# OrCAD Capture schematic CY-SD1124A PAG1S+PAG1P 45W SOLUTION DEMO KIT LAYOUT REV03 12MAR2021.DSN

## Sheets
1 PAGE02_PULSE TRANSFORMER BOARD: size A4; title: CYPRESS 45W MOBILE CHARGER DEMO KIT CY-SD1124A; rev: 03; note: 630-XXXXX-XX
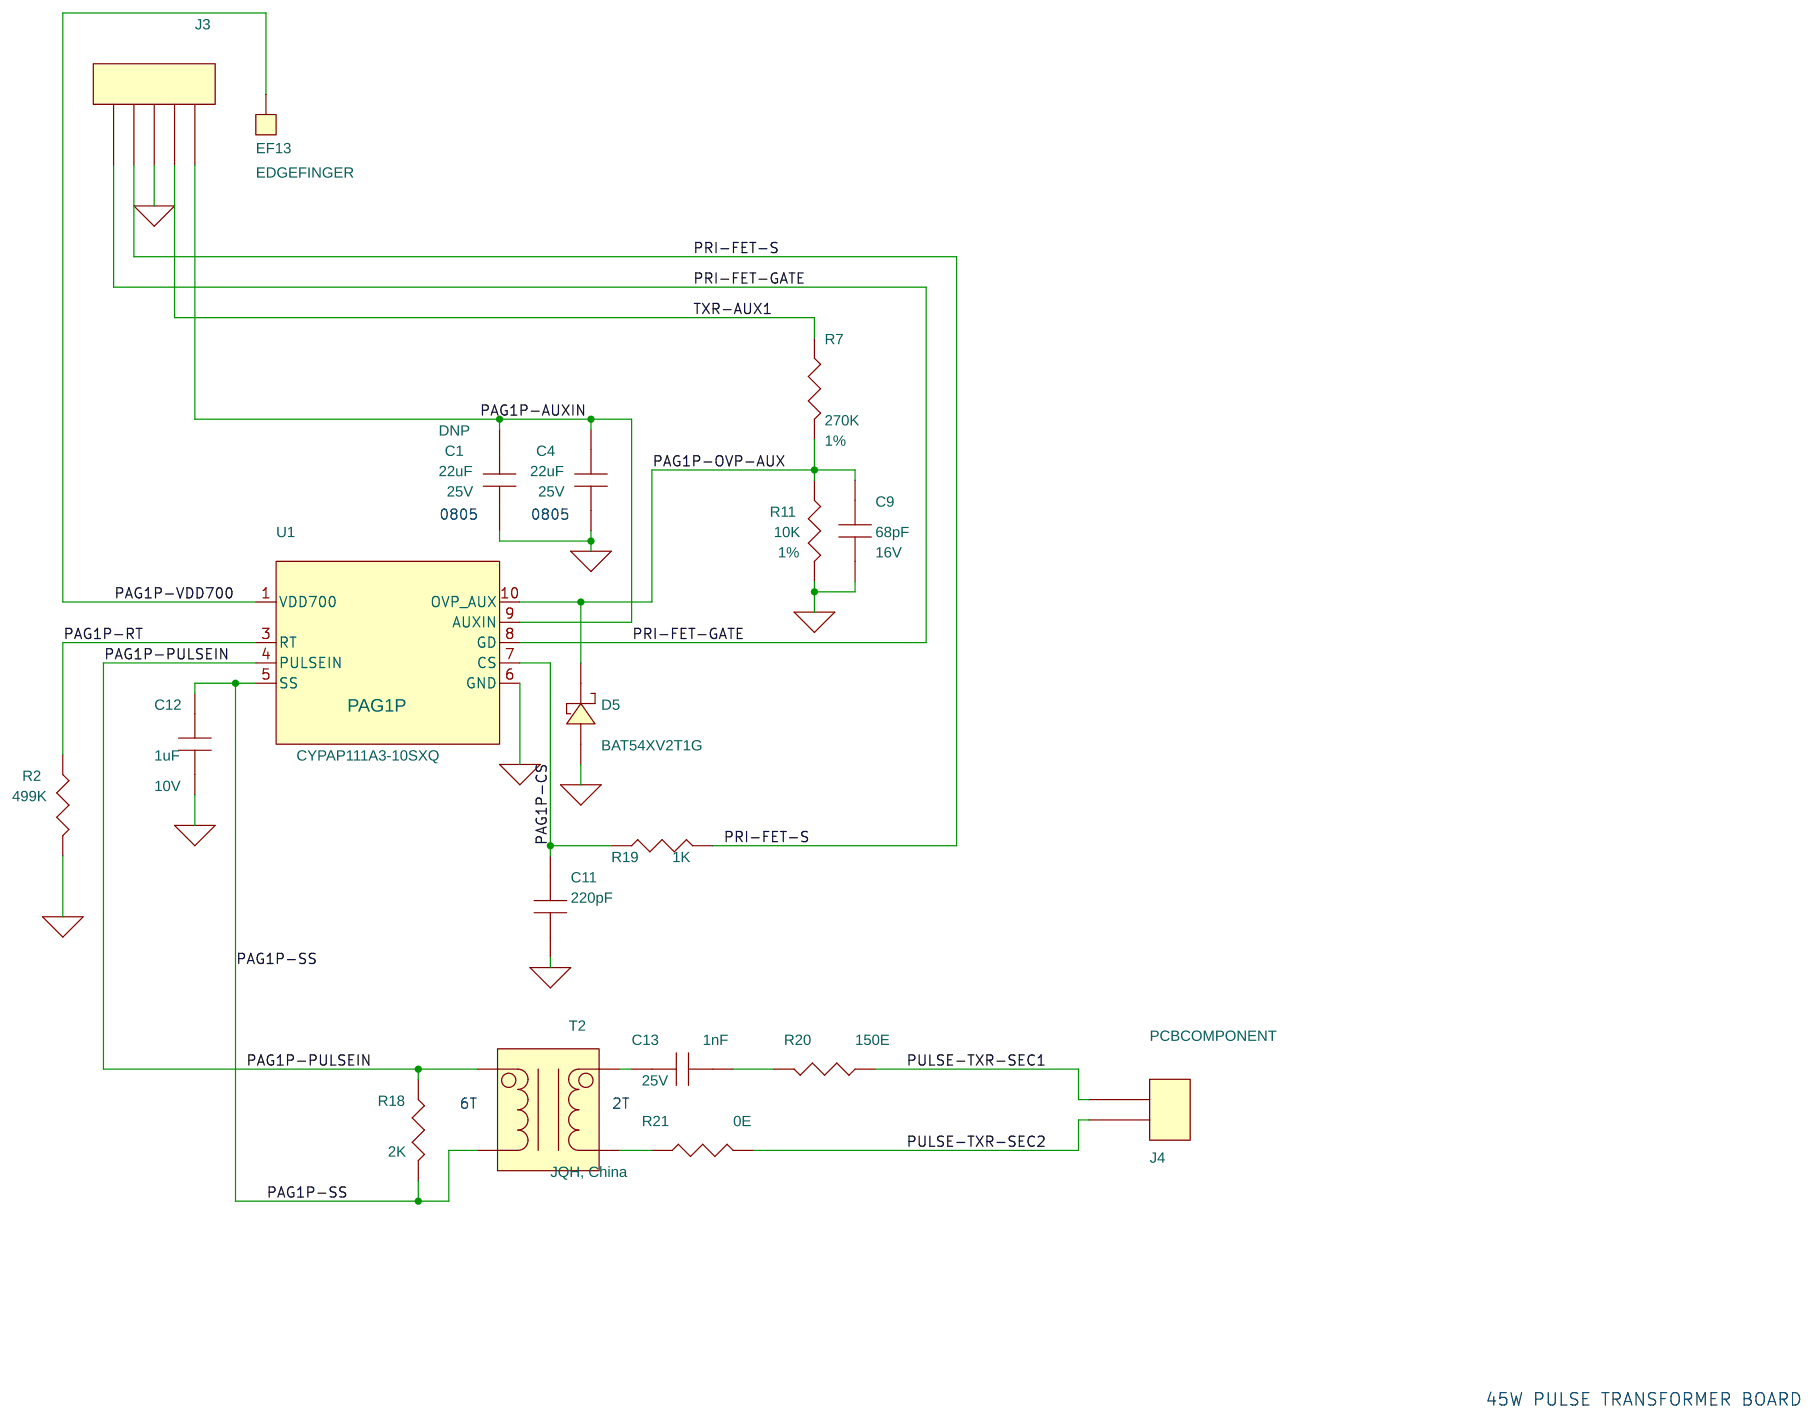
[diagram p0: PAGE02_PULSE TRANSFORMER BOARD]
2 PAGE03_SECONDARY BOARD: size A3
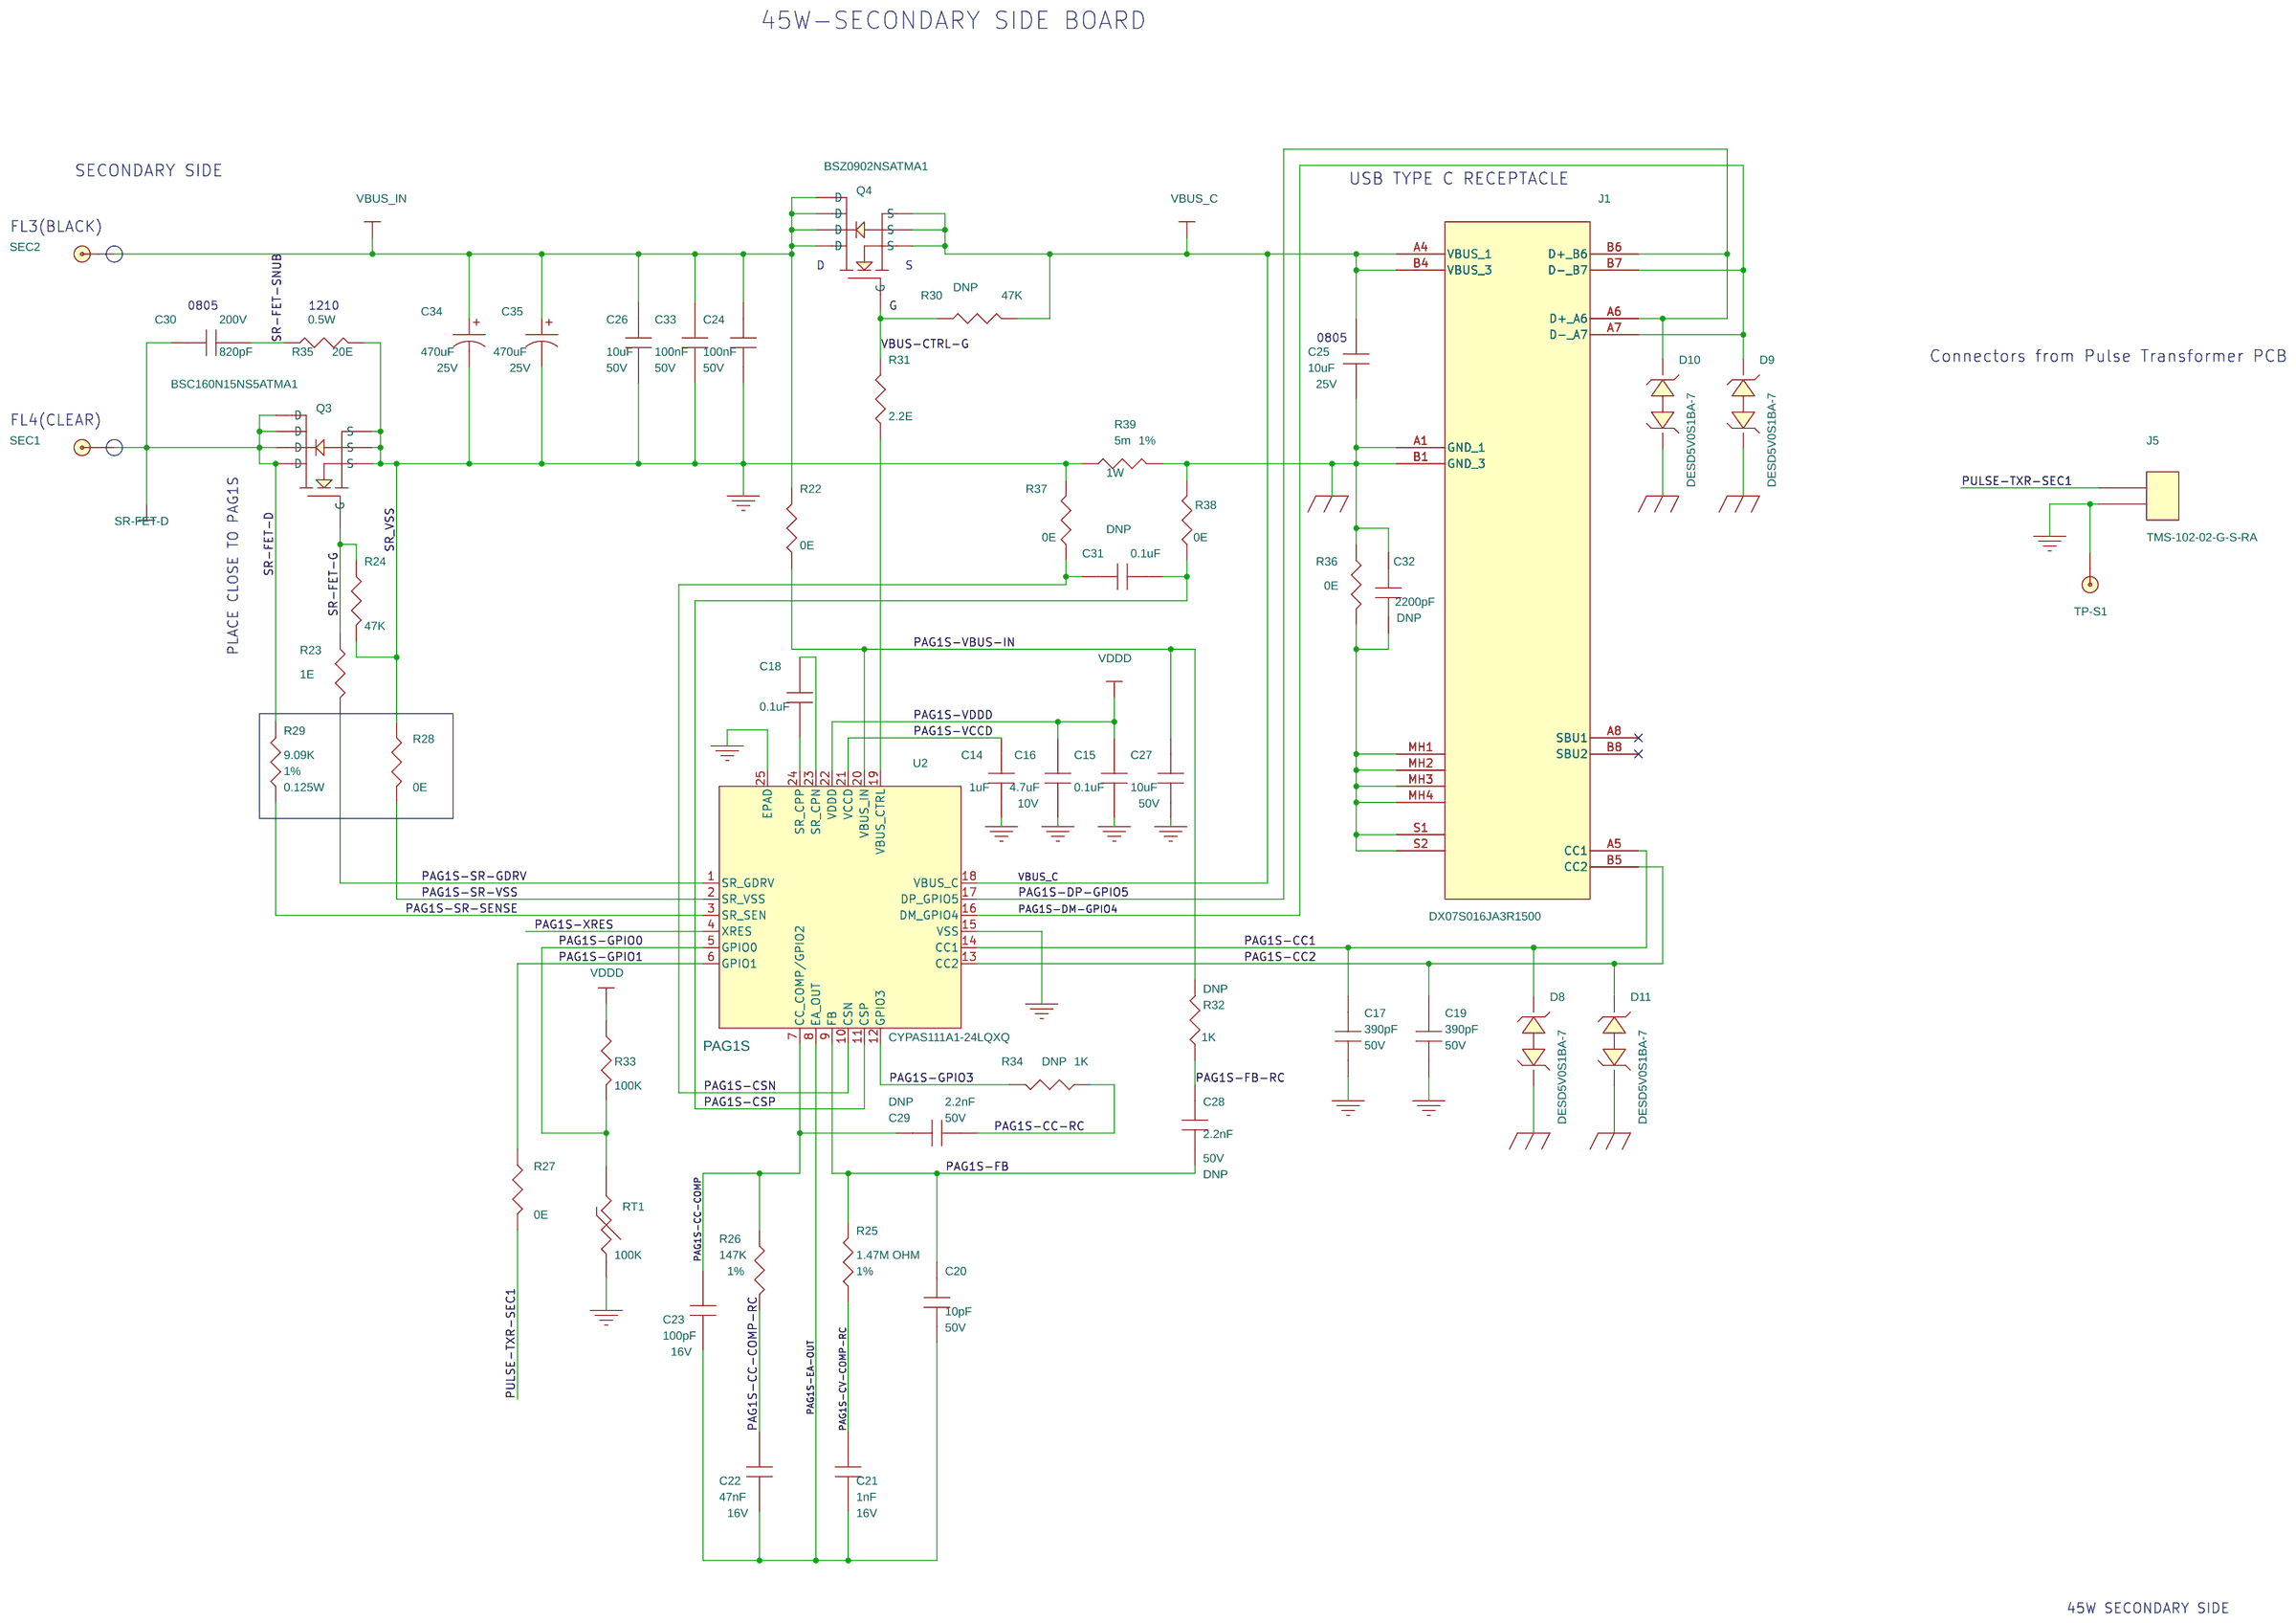
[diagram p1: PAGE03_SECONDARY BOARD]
3 PAGE04_REVISION HISTORY
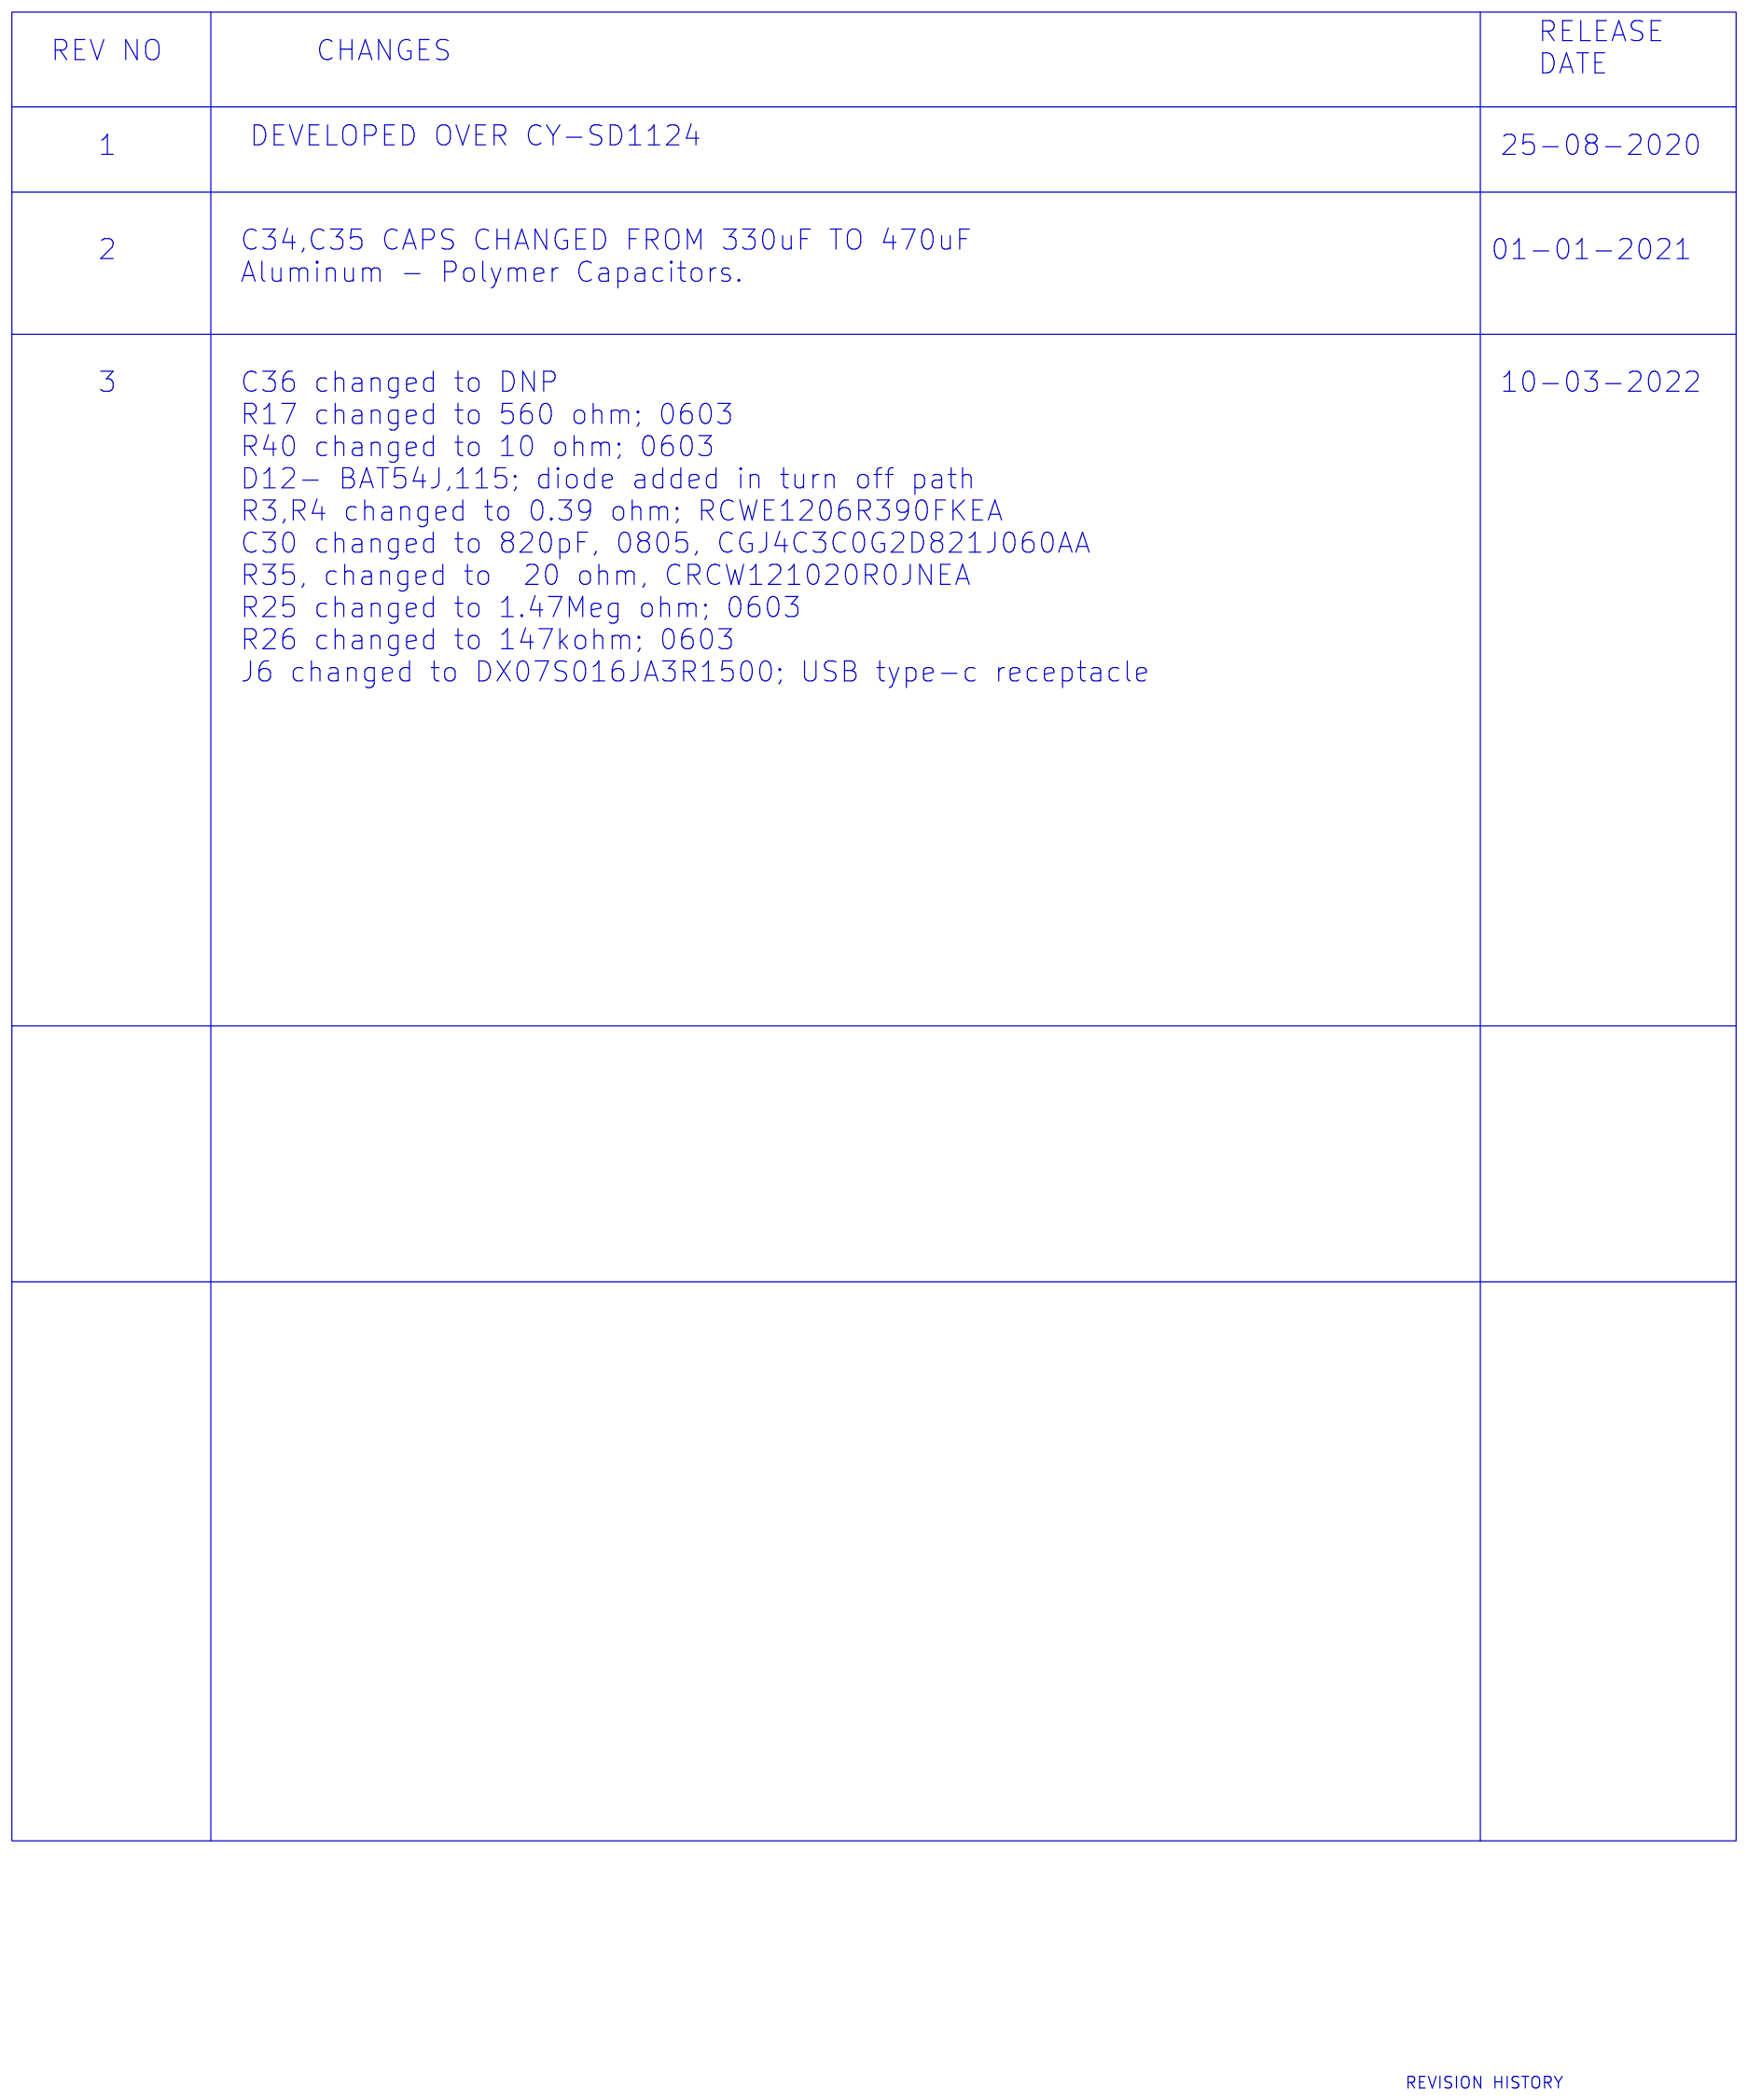
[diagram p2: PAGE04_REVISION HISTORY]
4 PAGE01_PRIMARY SIDE BOARD: size A3
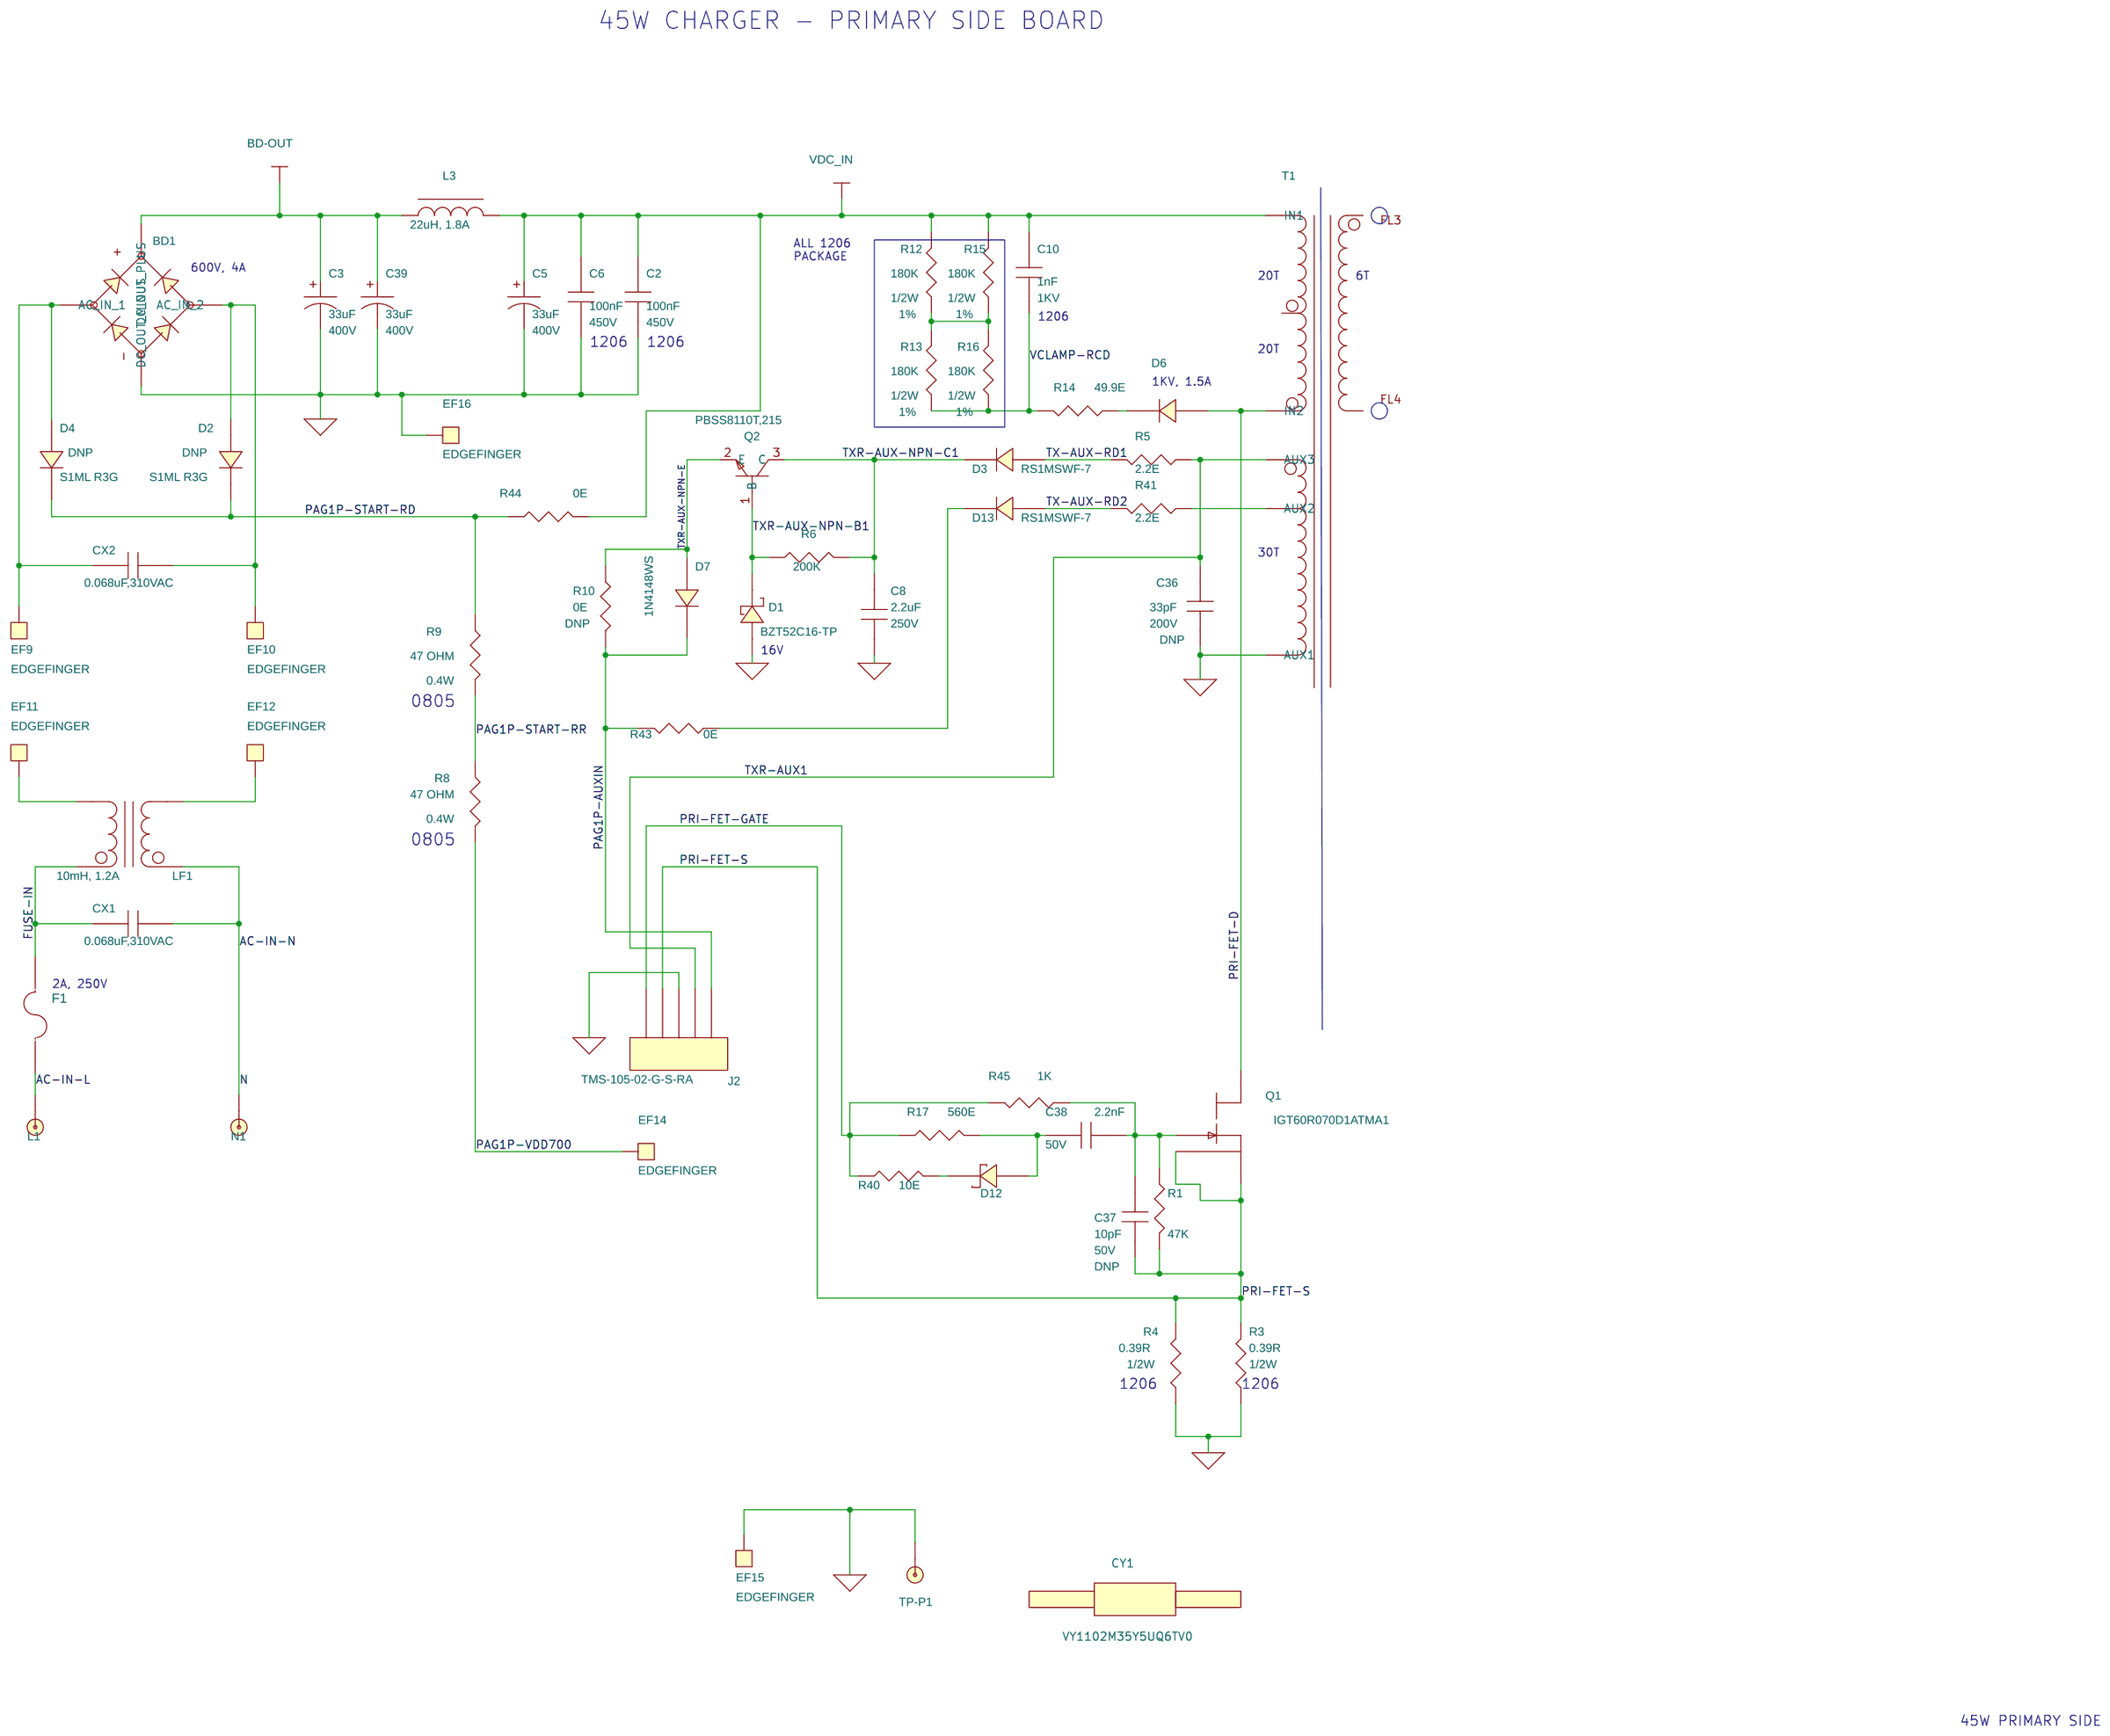
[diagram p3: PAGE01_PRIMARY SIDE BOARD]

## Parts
sheet PAGE01_PRIMARY SIDE BOARD
BD1  Z4DGP406L-HF  [Z4DGP406L-HF]
C2  100nF  [CAPCC1206]
C3  33uF  [CAPPRD600W60D1000H2150]
C5  33uF  [CAPPRD600W60D1000H2150]
C6  100nF  [CAPCC1206]
C8  2.2uF  [CAP_5750]
C10  1nF  [CAPCC1206]
C36  33pF  [CAPCC0603]
C37  10pF  [CAPCC0603]
C38  2.2nF  [CAPCC0603]
C39  33uF  [CAPPRD600W60D1000H2150]
CX1  0.068uF,310VAC  [BFC233820683]
CX2  0.068uF,310VAC  [R463I26804001M]
CY1  VY1102M35Y5UQ6TV0
D1  BZT52C16-TP  [BZT52C12-TP_SOD123]
D2  S1ML R3G  [SODFL360X180X143L60X100N]
D3  RS1MSWF-7  [SODFL350X180X115L60X107N]
D4  S1ML R3G  [SODFL360X180X143L60X100N]
D6  RS2MA-13-F  [DIOC430X260X230L114]
D7  1N4148WS  [sodfl250x125x90l60x30n_1]
D12  BAT54J,115  [SODFL250X125X90L60X30N]
D13  RS1MSWF-7  [SODFL350X180X115L60X107N]
EF9  EDGEFINGER  [EDGEFINGER]
EF10  EDGEFINGER  [EDGEFINGER]
EF11  EDGEFINGER  [EDGEFINGER1]
EF12  EDGEFINGER  [EDGEFINGER1]
EF14  EDGEFINGER  [EDGEFINGER]
EF15  EDGEFINGER  [EDGEFINGER1]
EF16  EDGEFINGER  [EDGEFINGER]
F1  2A Fuse  [FUSE_C310FH-2-RE-TR1-1]
J2  TMS-105-02-G-S-RA  [TMS-105-02-G-S-RA]
L1  TEST_POINT  [TP-43R_S_2]
L3  22uH, 1.8A  [INDU_7447462220]
LF1  10mH, 1.2A  [CJ5094-CL]
N1  TEST_POINT  [TP-43R_S_1]
Q1  IGT60R070D1ATMA1  [IGT60R070D1]
Q2  PBSS8110T,215  [SOT23-3P95_240X100L40X44N]
R1  47K  [RESC0603]
R3  0.39R  [RESC1206]
R4  0.39R  [RESC1206]
R5  2.2E  [RESC0603]
R6  200K  [RESC0603]
R8  47 OHM  [RESC0805]
R9  47 OHM  [RESC0805]
R10  0E  [RESC0603]
R12  180K  [RESC1206]
R13  180K  [RESC1206]
R14  49.9E  [RESC1206]
R15  180K  [RESC1206]
R16  180K  [RESC1206]
R17  560E  [RESC0603]
R40  10E  [RESC0603]
R41  2.2E  [RESC0603]
R43  0E  [RESC0603]
R44  0E  [RESC0805]
R45  1K  [RESC0603]
T1  RM8 CORE  [RM8]
TP-P1  TEST_POINT  [TP-43R_S_1]
sheet PAGE02_PULSE TRANSFORMER BOARD
C1  22uF  [CAPCC0805]
C4  22uF  [CAPCC0805]
C9  68pF  [CAPCC0603]
C11  220pF  [CAPCC0603]
C12  1uF  [CAPCC0603]
C13  1nF  [CAPCC0603]
D5  BAT54XV2T1G  [BAT54XV2T1G_SOD523]
EF13  EDGEFINGER  [EDGEFINGER1]
J3  PCBCOMPONENT  [PCBCOMPONENT5PIN]
J4  PCBCOMPONENT  [PCBCOMP2PIN]
R2  499K  [RESC0603]
R7  270K  [RESC0603]
R11  10K  [RESC0603]
R18  2K  [RESC0603]
R19  1K  [CAPCC0402]
R20  150E  [RESC0603]
R21  0E  [RESC0603]
T2  1:3  [RDL_R113426000ALT]
U1  PAG1P  [SOIC100P600X175-10N_CYPS]
sheet PAGE03_SECONDARY BOARD
C14  1uF  [CAPCC0402]
C15  0.1uF  [CAPCC0402]
C16  4.7uF  [CAPCC0402]
C17  390pF  [CAPCC0603]
C18  0.1uF  [CAPCC0402]
C19  390pF  [CAPCC0603]
C20  10pF  [CAPCC0603]
C21  1nF  [CAPCC0603]
C22  47nF  [CAPCC0603]
C23  100pF  [CAPCC0603]
C24  100nF  [CC1210]
C25  10uF  [CAPCC0805]
C26  10uF  [CAPCC1206]
C27  10uF  [CAPCC1206]
C28  2.2nF  [CAPCC0603]
C29  2.2nF  [CAPCC0603]
C30  820pF  [CAPCC0805]
C31  0.1uF  [CAPCC0603]
C32  2200pF  [CAPCC0603]
C33  100nF  [CC1210]
C34  470uF  [CAPPRD350W60D800H1350P]
C35  470uF  [CAPPRD350W60D800H1350P]
D8  DESD5V0S1BA-7  [DIO-SOD323]
D9  DESD5V0S1BA-7  [DIO-SOD323]
D10  DESD5V0S1BA-7  [DIO-SOD323]
D11  DESD5V0S1BA-7  [DIO-SOD323]
J1  DX07S016JA3R1500  [JAE_DX07S016JA3R1500]
J5  TMS-102-02-G-S-RA  [TMS-102-02-G-S-RA]
Q3  BSC160N15NS5ATMA1  [TDSON8]
Q4  BSZ0902NSATMA1  [TSDSON65P330X330X110-8N_A]
R22  0E  [RESC0603]
R23  1E  [RESC0603]
R24  47K  [RESC0603]
R25  1.47M OHM  [RESC0603]
R26  147K  [RESC0603]
R27  0E  [RESC0603]
R28  0E  [RESC0603]
R29  9.09K  [RESC0805]
R30  47K  [RESC0603]
R31  2.2E  [RESC0603]
R32  1K  [RESC0603]
R33  100K  [RESC0603]
R34  1K  [RESC0603]
R35  20E  [1210]
R36  0E  [RESC0603]
R37  0E  [RESC0603]
R38  0E  [RESC0603]
R39  5m  [RESC1206]
RT1  100K  [RESC0805]
SEC1  TEST_POINT  [TP-43R_S_1]
SEC2  TEST_POINT  [TP-43R_S_1]
TP-S1  TEST_POINT  [TP-43R_S_1]
U2  PAG1S  [QFN50P400X400X60-25T275X275N]

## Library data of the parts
BD1 = BR805D_2: BRIDGE RECT 1PHASE 600V 4A Z4-D; BOARD ID: 1; BOARDID: 1; DIGIKEY-PART NUMBER: 641-1502-1-ND; Manufacturer: Comchip Technology; PRICE: 1.06
C2 C6 = 0_0.01uF-50V-10%-X7R-0603: CAP CER 100nF 450V X7T 1206; BOARD ID: 1; BOARDID: 1; DIGIKEY-PART NUMBER: 445-7758-1-ND; MFG Part number: C3216X7T2W104K160AA; Manufacturer: TDK Corporation; Price: 0.7; TOLERANCE: <Tolerance>; Voltage: 450V
C3 C5 C39 = CAP_2: CAP ALUM 33UF 20% 400V RADIAL; BOARD ID: 1; BOARDID: 1; MFG Part number: EKXL401ELL330MJ30S; Manufacturer: United Chemi-Con; Manufaturer: Rubycon; Package: RAD; Voltage: 400V
C8 = 0_0.01uF-50V-10%-X7R-0603: CAP CER 2.2UF 250V X7T 2220; BOARD ID: 1; BOARDID: 1; DIGIKEY-PART NUMBER: 445-7775-1-ND; MFG Part number: C5750X7T2E225K250KA; Manufacturer: TDK Corporation; Price: 3.53; Voltage: 250V
C10 = 0_0.01uF-50V-10%-X7R-0603: CAP CER 1206 1NF 1000V X7R 10%; BOARD ID: 1; BOARDID: 1; DIGIKEY-PART NUMBER: 399-16677-1-ND; MFG Part number: C1206C102KDRACAUTO; Manufacturer: KEMET; Price: 0.32; TOLERANCE: <Tolerance>; Voltage: 1KV
C36 = 0_0.01uF-50V-10%-X7R-0603: CAP CER 33PF 200V C0G/NP0 0603; BOARD ID: 1; BOARDID: 1; DIGIKEY-PART NUMBER: 399-9059-1-ND; DNP: DNP; MFG Part number: C0603C330J2GACTU; Manufacturer: KEMET; Price: 0.1; Voltage: 200V
C37 = 0_0.01uF-50V-10%-X7R-0603: CAP CER 10PF 50V NPO 0603; BOARD ID: 1; BOARDID: 1; DIGIKEY-PART NUMBER: 311-4025-1-ND; DNP: DNP; MFG Part number: CC0603KRNPO9BN100; Manufacturer: Yageo; Price: 0.1; Voltage: 50V
C38 = 0_0.01uF-50V-10%-X7R-0603: CAP CER SMD 0603 2200PF 10% X7R 50V; BOARD ID: 1; BOARDID: 1; DIGIKEY-PART NUMBER: 399-17586-1-ND; MFG Part number: C0603C222K5RAC7411; Manufacturer: KEMET; Price: 0.1; Voltage: 50V
CX1 = 0_0.01uF-50V-10%-X7R-0603: CAP FILM 0.068UF 20% 630VDC RAD; BOARD ID: 4; BOARDID: 2; DIGIKEY-PART NUMBER: BC1619-ND; Manufacturer: Vishay BC Components; Package: RAD; Price: 1.32; TOLERANCE: <Tolerance>; Voltage: 310VAC
CX2 = 0_0.01uF-50V-10%-X7R-0603: CAP FILM 0.068UF 20% 630VDC RAD; BOARD ID: 4; BOARDID: 1; DIGIKEY-PART NUMBER: 399-18723-ND; Manufacturer: KEMET; Package: RAD; Price: 0.45; TOLERANCE: <Tolerance>; Voltage: 310VAC
CY1 = CD45-B2GA221K-GKA: CAP CER 1000PF 760VAC Y5U RADIAL; BOARD ID: 1; BOARDID: 1; DIGIKEY-PART NUMBER: BC5260CT-ND; Manufacturer: Vishay BC Components; Price: 0.41
D1 = DIODE_SCHOTTKY_19: DIODE ZENER 16V 200MW SOD123; BOARD ID: 1; BOARDID: 1; DIGIKEY-PART NUMBER: BZT52C16-TPMSCT-ND; Manufacturer: Micro Commercial Co; Price: 0.21
D2 D4 = DIODE_15: DIODE GEN PURP 1KV 1A SUB SMA; BOARD ID: 1; BOARDID: 1; DIGIKEY-PART NUMBER: S1MLR3GCT-ND; DNP: DNP; Manufacturer: Taiwan Semiconductor Corporation; Price: 0.39
D3 D13 = DIODE_17: DIODE GEN PURP 1KV 1A SOD123F; BOARD ID: 1; BOARDID: 1; DIGIKEY-PART NUMBER: RS1MSWF-7DICT-ND; Manufacturer: Diodes Incorporated; Price: 0.48
D6 = DIODE_13: DIODE GEN PURP 1KV 1.5A SMA; BOARD ID: 1; BOARDID: 1; DIGIKEY-PART NUMBER: RS2MA-FDICT-ND; Manufacturer: Diodes Incorporated; PRICE: 0.41
D7 = DIODE_15: DIODE GEN PURP 75V 150MA SOD323F; BOARD ID: 1; BOARDID: 1; DIGIKEY-PART NUMBER: 1N4148WSFSCT-ND; Manufacturer: ON Semiconductor; Price: 0.17
D12 = DIODE_18: DIODE SCHOTTKY 30V 200MA SOD323F; DIGIKEY-PART NUMBER: 1727-4818-1-ND; Manufacturer: Nexperia USA Inc.; PRICE: 0.33
EF9 EF10 EF14 EF16 = EDGEFINGER: BOARD ID: 1; BOARDID: 1
EF11 EF12 = EDGEFINGER: BOARD ID: 4; BOARDID: 2
EF13 EF15 = EDGEFINGER: BOARD ID: 4; BOARDID: 3
F1 = Fuse_2: Fuses with Leads (Through Hole) 2A 250V Epoxy Coated; BOARD ID: 4; BOARDID: 2; LatestRevisionDate: 17-Jul-2002; LatestRevisionNote: Re-released for DXP Platform.; MFG Part number: C310FH-2-RE-TR1; Manufacturer: Coiltronics / Eaton; PackageReference: PIN-W2/E2.8; Published: 8-Jun-2000; Publisher: Altium Limited
J2 = CON6_0: 1.27mm pich Through Hole Right Angle Connector; BOARDID: 1; Manufacturer: Samtec Inc.
L1 N1 = TEST_POINT: BOARD ID: 4; BoardID: 2
L3 = INDUCTOR_PAG1S_1: FIXED IND 22UH 1.8A 130 MOHM TH; BOARD ID: 1; BOARDID: 1; Current: 300mA; DIGIKEY-PART NUMBER: 732-2570-ND; MFG Part number: 7447462220; Manufacturer: Wurth Electronics Inc.; PRICE: 0.89
LF1 = INDUCTOR_IRON_8: CMC 10mH 1.2A 2LN SMD; BOARD ID: 4; BOARDID: 2; Manufacturer: coilcraft
Q1 = 2N6802_1: N-Channel 600V 31A (Tc) 125W (Tc) Surface Mount PG-HSOF-8-3; BOARD ID: 1; BOARDID: 1; DIGIKEY-PART NUMBER: IGT60R070D1ATMA1CT-ND; Manufacturer: Infineon Technologies; Price: 22.33
Q2 = 2N1070_1: TRANS NPN 100V 1A SOT23; BOARD ID: 1; BOARDID: 1; DIGIKEY-PART NUMBER: 1727-3940-1-ND; Manufacturer: Nexperia USA Inc.; Price: 0.45
R1 = 330_ohm_5%_0805_0: RES SMD 47K OHM 1% 1/10W 0603; BOARD ID: 1; BOARDID: 1; DIGIKEY-PART NUMBER: 311-47.0KHRCT-ND; MFG Part number: RC0603FR-0747KL; Manufacturer: Yageo; Mfr_Name: Yageo; Mfr_Part#: ERJ-3GEY0R00V; PRICE: 0.1
R3 = RESISTOR: RES 0.39 OHM 1% 1/2W 1206; BOARD ID: 1; BoardID: 1; DIGIKEY-PART NUMBER: RCWE.39EDKR-ND; MFG Part number: RCWE1206R390FKEA; Manufacturer: Vishay Dale; Package: 1206; Price: 0.58; Wattage: 1/2W
R4 = RESISTOR: RES 0.39 OHM 1% 1/2W 1206; Assy: DNP; BOARD ID: 1; BoardID: 1; DIGIKEY-PART NUMBER: RCWE.39EDKR-ND; MFG Part number: RCWE1206R390FKEA; Manufacturer: Vishay Dale; Package: 1206; Price: 0.58; Wattage: 1/2W
R5 R41 = RESISTOR: RES SMD 2.2 OHM 1% 1/10W 0603; Assy: DNP; BOARD ID: 1; BoardID: 1; DIGIKEY-PART NUMBER: 311-2.2HRCT-ND; MFG Part number: RC0603FR-072R2L; Manufacturer: Yageo; Package: 0603; Price: 0.1
R6 = RESISTOR: RES SMD 200K OHM 1% 1/10W 0603; BOARD ID: 1; BoardID: 1; DIGIKEY-PART NUMBER: P200KHCT-ND; MFG Part number: ERJ-3EKF2003V; Manufacturer: Panasonic Electronic Components; Price: 0.1
R8 R9 = 330_ohm_5%_0805_0: RES SMD 47 OHM 5% 0.4W 0805; ALTERNATE PARTNUMBER 1: RHM47KCT-ND; BOARD ID: 1; BOARDID: 1; DIGIKEY-PART NUMBER: RHM47KCT-ND; MFG Part number: ESR10EZPJ470; Manufacturer: Rohm Semiconductor; PRICE: 0.1; Wattage: 0.4W
R10 = 330_ohm_5%_0805_0: RES SMD 0 OHM JUMPER 1/4W 0603; BOARD ID: 1; BOARDID: 1; DIGIKEY-PART NUMBER: 541-0.0SBCT-ND; DNP: DNP; MFG Part number: CRCW06030000Z0EAHP; Manufacturer: Vishay Dale; Mfr_Name: Yageo; Mfr_Part#: RC0402FR-07100KL; PRICE: 0.17
R12 R13 R15 R16 = RESISTOR: CRGP 1206 180K 1% 1/2W; BOARD ID: 1; BoardID: 1; DIGIKEY-PART NUMBER: A130565CT-ND; MFG Part number: CRGP1206F180K; Manufacturer: TE Connectivity Passive Product; Package: 1206; Price: 0.33; Tolerance: 1%; Wattage: 1/2W
R14 = 330_ohm_5%_0805_0: RES SMD 49.9 OHM 1% 1/4W 1206; BOARD ID: 1; BOARDID: 1; DIGIKEY-PART NUMBER: 311-49.9FRCT-ND; MFG Part number: RC1206FR-0749R9L; Manufacturer: Yageo; PRICE: 0.1
R17 = 330_ohm_5%_0805_0: RES SMD 560 OHM 1% 1/10W 0603; BOARD ID: 1; BOARDID: 1; DIGIKEY-PART NUMBER: P560HTR-ND; MFG Part number: ERJ-3EKF5600V; Manufacturer: Panasonic Electronic Components; PRICE: 0.1
R40 = 330_ohm_5%_0805_0: RES 10 OHM 5% 1/10W 0603 SMD; BOARD ID: 1; BOARDID: 1; DIGIKEY-PART NUMBER: 10-ERJ-U03J100VCT-ND; MFG Part number: ERJ-U03J100V; Manufacturer: Panasonic Electronic Components; PRICE: 0.1
R43 = 330_ohm_5%_0805_0: RES SMD 0 OHM JUMPER 1/4W 0603; BOARD ID: 1; BOARDID: 1; DIGIKEY-PART NUMBER: 541-0.0SBCT-ND; MFG Part number: CRCW06030000Z0EAHP; Manufacturer: Vishay Dale; Mfr_Name: Yageo; Mfr_Part#: RC0402FR-07100KL; PRICE: 0.17
R44 = 330_ohm_5%_0805_0: RES SMD 0 OHM JUMPER 0.4W 0805; ALTERNATE PARTNUMBER 1: RHM47KCT-ND; BOARD ID: 1; BOARDID: 1; DIGIKEY-PART NUMBER: 541-2827-1-ND; MFG Part number: RCS08050000Z0EA; Manufacturer: Vishay Dale; PRICE: 0.15; Wattage: 0.4W
R45 = 330_ohm_5%_0805_0: RES SMD 1K OHM 1% 1/10W 0603; BOARD ID: 1; BOARDID: 1; DIGIKEY-PART NUMBER: 311-1.00KHRCT-ND; MFG Part number: RC0603FR-071KL; Manufacturer: Yageo; PRICE: 0.1
T1 = PA5222NL_37: POWER TRANSFORMER_RM8 CORE; BOARD ID: 1; BOARDID: 1; MFG Part number: EL-TXR-19-01-005; Manufacturer: <Manufacturer>
TP-P1 = TEST_POINT: BOARD ID: 1; BOARDID: 1
C1 = 0_0.01uF-50V-10%-X7R-0603: CAP CER 22UF 25V X5R 0805; BOARD ID: 1; BOARDID: 3; DIGIKEY-PART NUMBER: 490-14661-1-ND; DNP: DNP; MFG Part number: GRM21BR61E226ME44K; Manufacturer: Murata Electronics North America; Price: 0.49; Voltage: 25V
C4 = 0_0.01uF-50V-10%-X7R-0603: CAP CER 22UF 25V X5R 0805; BOARD ID: 1; BOARDID: 3; DIGIKEY-PART NUMBER: 490-14661-1-ND; MFG Part number: GRM21BR61E226ME44K; Manufacturer: Murata Electronics North America; Price: 0.49; Voltage: 25V
C9 = 0_0.01uF-50V-10%-X7R-0603: CAP CER 68PF 16V C0G/NP0 0603; BOARD ID: 1; BOARDID: 3; DIGIKEY-PART NUMBER: 732-7765-1-ND; MFG Part number: 885012006022; Manufacturer: Wurth Electronics Inc.; Price: 0.1; Voltage: 16V
C11 = 0_0.01uF-50V-10%-X7R-0603: CAP CER 220PF 10V C0G/NP0 0603; BOARD ID: 1; BOARDID: 3; DIGIKEY-PART NUMBER: 399-14963-1-ND; MFG Part number: C0603C221J8GAC7867; Manufacturer: KEMET; Price: 0.32; Voltage: 10V
C12 = 0_0.01uF-50V-10%-X7R-0603: CAP CER 0603 1UF 10V X7R 10%; BOARD ID: 1; BOARDID: 3; DIGIKEY-PART NUMBER: 399-17705-1-ND; MFG Part number: C0603C105K8RACAUTO; Manufacturer: KEMET; Price: 0.13; Voltage: 10V
C13 = 0_0.01uF-50V-10%-X7R-0603: CAP CER 1000PF 25V C0G/NP0 0603; BOARD ID: 3; BOARDID: 3; DIGIKEY-PART NUMBER: 399-7830-1-ND; MFG Part number: C0603C102J3GACTU; Manufacturer: KEMET; Price: 0.1; TOLERANCE: C0G/NPO; Voltage: 25V
D5 = DIODE_SCHOTTKY_21: DIODE SCHOTTKY 30V 200MA SOD523; BOARD ID: 1; BOARDID: 3; DIGIKEY-PART NUMBER: BAT54XV2T1GOSCT-ND; Manufacturer: ON Semiconductor; Price: 0.22
J3 = CON6_1: BOARDID: 3
J4 = CON2: PCB COMPONENT; BOARDID: 3
R2 = 330_ohm_5%_0805_0: RES SMD 499K OHM 1% 1/8W 0603; BOARD ID: 1; BOARDID: 3; DIGIKEY-PART NUMBER: 749-1661-1-ND; MFG Part number: MCT06030C4993FP500; Manufacturer: Vishay Beyschlag; Mfr_Name: Vishay Beyschlag; Mfr_Part#: RC0402FR-07100KL; Mfr_Part_Number: MCT06030C4993FP500; PRICE: 0.18
R7 = 330_ohm_5%_0805_0: RES 270K OHM 1% 1/10W 0603; BOARD ID: 1; BOARDID: 3; DIGIKEY-PART NUMBER: RMCF0603FT270KCT-ND; MFG Part number: RMCF0603FT270K; Manufacturer: Stackpole Electronics Inc; PRICE: 0.1; Tolerance: 1%
R11 = 330_ohm_5%_0805_0: RES SMD 10K OHM 1% 1/10W 0603; BOARD ID: 1; BOARDID: 3; DIGIKEY-PART NUMBER: 311-10.0KHRCT-ND; MFG Part number: RC0603FR-0710KL; Manufacturer: Yageo; PRICE: 0.1; VOLTAGE: 1%; Wattage: 0.1W
R18 = 330_ohm_5%_0805_0: RES SMD 2K OHM 1% 1/10W 0603; BOARD ID: 1; BOARDID: 3; DIGIKEY-PART NUMBER: 311-2.00KHRCT-ND; MFG Part number: RC0603FR-072KL; Manufacturer: Yageo; PRICE: 0.1
R19 = 330_ohm_5%_0805_0: RES SMD 1K OHM 1% 1/16W 0402; BOARD ID: 1; BOARDID: 3; DIGIKEY-PART NUMBER: 311-1.00KLRCT-ND; MFG Part number: RC0402FR-071KL; Manufacturer: Yageo; PRICE: 0.1
R20 = 330_ohm_5%_0805_0: RES SMD 150 OHM 1% 1/10W 0603; BOARD ID: 3; BOARDID: 3; DIGIKEY-PART NUMBER: 311-150HRCT-ND; MFG Part number: RC0603FR-07150RL; Manufacturer: Yageo; PRICE: 0.1
R21 = 330_ohm_5%_0805_0: RES SMD 0 OHM JUMPER 1/4W 0603; BOARD ID: 3; BOARDID: 3; DIGIKEY-PART NUMBER: 541-0.0SBCT-ND; MFG Part number: CRCW06030000Z0EAHP; Manufacturer: Vishay Dale; Mfr_Name: Yageo; Mfr_Part#: ERJ-3GEY0R00V; PRICE: 0.17
T2 = TRANSFORMER_13: Pulse transformer, 1:3, 4.8uH, 3KV isolation voltage; BOARD ID: 3; BOARDID: 3; MFG Part number: LCL-T6-5138A; Manufacturer: JQH, China
U1 = PAG1P_3: PRIMARY SIDE STARTUP CONTROLLER; BOARD ID: 1; BOARDID: 3; MFG Part number: CYPAP111A3-10SXQ; Manufacturer: CYPRESS SEMICONDUCTOR
C14 = 0_0.01uF-50V-10%-X7R-0603: CAP CER 1UF 16V X5R 0402; BOARD ID: 2; BOARDID: 4; DIGIKEY-PART NUMBER: 1276-1447-1-ND; MFG Part number: CL05A105MO5NNNC; Manufacturer: Samsung Electro-Mechanics; Price: 0.1; Voltage: 16V
C15 C18 = 0_0.01uF-50V-10%-X7R-0603: CAP CER 0.1UF 25V X7R 0402; BOARD ID: 2; BOARDID: 4; DIGIKEY-PART NUMBER: 399-14148-1-ND; MFG Part number: C0402C104K3RAC7867; Manufacturer: KEMET; Price: 0.26; Voltage: 25V
C16 = 0_0.01uF-50V-10%-X7R-0603: CAP CER 4.7UF 10V X5R 0402; BOARD ID: 2; BOARDID: 4; DIGIKEY-PART NUMBER: 490-14306-1-ND; MFG Part number: GRM155R61A475MEAAD; Manufacturer: Murata Electronics; Price: 0.23; Voltage: 10V
C17 C19 = 0_0.01uF-50V-10%-X7R-0603: CAP CER 390PF 50V X7R 0603; BOARD ID: 2; BOARDID: 4; DIGIKEY-PART NUMBER: 311-1187-1-ND; MFG Part number: CC0603KRX7R9BB391; Manufacturer: Yageo; Price: 0.1; Voltage: 50V
C20 = 0_0.01uF-50V-10%-X7R-0603: CAP CER 10PF 50V NP0 0603; BOARD ID: 2; BOARDID: 4; DIGIKEY-PART NUMBER: 445-14053-1-ND; MFG Part number: C1608NP01H100D080AA; Manufacturer: TDK Corporation; Price: 0.21; Voltage: 50V
C21 = 0_0.01uF-50V-10%-X7R-0603: CAP CER SMD 0603 1000PF 10% X7R; BOARD ID: 2; BOARDID: 4; DIGIKEY-PART NUMBER: 399-17565-1-ND; MFG Part number: C0603C102K4RACAUTO; Manufacturer: KEMET; Price: 0.14; Voltage: 16V
C22 = 0_0.01uF-50V-10%-X7R-0603: CAP CER 0.047UF 16V X7R 0603; BOARD ID: 2; BOARDID: 4; DIGIKEY-PART NUMBER: 311-1801-1-ND; MFG Part number: CC0603KRX7R7BB473; Manufacturer: Yageo; Price: 0.1; Voltage: 16V
C23 = 0_0.01uF-50V-10%-X7R-0603: CAP CER 100PF 16V X7R 0603; BOARD ID: 2; BOARDID: 4; DIGIKEY-PART NUMBER: 399-14937-1-ND; MFG Part number: C0603C101K4RAC7867; Manufacturer: KEMET; Price: 0.25; Voltage: 16V
C24 C33 = 0_0.01uF-50V-10%-X7R-0603: CAP CER 0.1UF 50V X7R 1210; BOARD ID: 2; BOARDID: 4; DIGIKEY-PART NUMBER: C1210C104K5RAC7210TR-ND; MFG Part number: C1210C104K5RAC7210; Manufacturer: KEMET; Price: 0.12; Voltage: 50V
C25 = 0_0.01uF-50V-10%-X7R-0603: CAP CER 10UF 25V X5R 0805; BOARD ID: 2; BOARDID: 4; DIGIKEY-PART NUMBER: 445-5985-1-ND; MFG Part number: C2012X5R1E106M125AB; Manufacturer: TDK Corporation; Price: 0.38; TOLERANCE: <Tolerance>; Voltage: 25V
C26 = 0_0.01uF-50V-10%-X7R-0603: CAP CER 10UF 50V X7R 1206; BOARD ID: 2; BOARDID: 4; DIGIKEY-PART NUMBER: 445-181412-1-ND; MFG Part number: CGA5L1X7R1H106K160AE; Manufacturer: TDK Corporation; Price: 1.38; Voltage: 50V
C27 = 0_0.01uF-50V-10%-X7R-0603: CAP CER 10UF 50V X7R 1206; BOARD ID: 2; BOARDID: 4; DIGIKEY-PART NUMBER: 445-180362-1-ND; MFG Part number: CGA5L1X7R1H106K160AC; Manufacturer: TDK Corporation; Price: 1.03; TOLERANCE: <Tolerance>; Voltage: 50V
C28 C29 = 0_0.01uF-50V-10%-X7R-0603: CAP CER SMD 0603 2200PF 10% X7R 50V; BOARD ID: 2; BOARDID: 4; DIGIKEY-PART NUMBER: 399-17586-1-ND; DNP: DNP; MFG Part number: C0603C222K5RAC7411; Manufacturer: KEMET; Price: 0.1; TOLERANCE: <Tolerance>; Voltage: 50V
C30 = 0_0.01uF-50V-10%-X7R-0603: 820pF ±5% 200V Ceramic Capacitor C0G 0805; Assy: DNP; BOARD ID: 2; BOARDID: 4; DIGIKEY-PART NUMBER: 445-9173-1-ND; MFG Part number: CGJ4C3C0G2D821J060AA; Manufacturer: TDK Corporation; Package: 1210; Price: 0.22; TOLERANCE: <Tolerance>; Voltage: 200V
C31 = 0_0.01uF-50V-10%-X7R-0603: CAP CER 0.1UF 35V X7R 0603; BOARD ID: 2; BOARDID: 4; DIGIKEY-PART NUMBER: 587-3354-1-ND; DNP: DNP; MFG Part number: GMK107B7104KAHT; Manufacturer: Taiyo Yuden; Price: 0.12; Voltage: 35V
C32 = 0_0.01uF-50V-10%-X7R-0603: CAP CER 2200PF 500V X7R 0603; BOARD ID: 2; BOARDID: 4; DIGIKEY-PART NUMBER: 399-14966-1-ND; DNP: DNP; MFG Part number: C0603C222KCRAC7867; Manufacturer: KEMET; Price: 0.27; TOLERANCE: <Tolerance>; Voltage: 500V
C34 C35 = CAP_2: CAP ALUM 330UF 20% 25V SMD; BOARD ID: 2; BOARDID: 4; DIGIKEY-PART NUMBER: 477AVG025MFBJ-ND; MFG Part number: 477AVG025MFBJ; Manufacturer: Illinois Capacitor; Package: RAD; RATED_VOLTAGE: 25V; Voltage: 25V
D8-D11 = TVS_DIODE_1: TVS DIODE 5V 14V SOD323; BOARD ID: 2; BOARDID: 4; DIGIKEY-PART NUMBER: DESD5V0S1BA-7DICT-ND; Manufacturer: Diodes Incorporated; Price: 0.36
J1 = USB-PD_TYPE-C_8: CONN USB-C RCPT 16 POS R/A SMT; Manufacturer: JAE Electronics
J5 = CON2: CONN HEADER R/A 2POS 1.27MM; BOARDID: 4; DIGIKEY-PART NUMBER: SAM12200-ND; Manufacturer: Samtec Inc.; Price: 0.38
Q3 = DMTH10H010LCT_5: MOSFET N-CH 150V 56A 8TDSON; BOARD ID: 2; BOARDID: 4; DIGIKEY-PART NUMBER: BSC160N15NS5ATMA1CT-ND; Manufacturer: Infineon Technologies; PRICE: 2.33
Q4 = DMTH10H010LCT_5: MOSFET N-CH 30V 40A TSDSON-8; BOARD ID: 2; BOARDID: 4; DIGIKEY-PART NUMBER: BSZ0902NSATMA1CT-ND; MFG Part number: BSZ0902NS; Manufacturer: Infineon Technologies; PRICE: 0.89
R22 R36-R38 = 330_ohm_5%_0805_0: RES SMD 0 OHM JUMPER 1/4W 0603; BOARD ID: 2; BOARDID: 4; DIGIKEY-PART NUMBER: 541-0.0SBCT-ND; MFG Part number: CRCW06030000Z0EAHP; Manufacturer: Vishay Dale; Mfr_Name: Yageo; Mfr_Part#: RC0402FR-07100KL; PRICE: 0.17
R23 = 330_ohm_5%_0805_0: RES SMD 1 OHM 1% 1/10W 0603; BOARD ID: 2; BOARDID: 4; DIGIKEY-PART NUMBER: 311-1.00HRCT-ND; MFG Part number: RC0603FR-071RL; Manufacturer: Yageo; Mfr_Name: Yageo; Mfr_Part#: RC0402FR-07100KL; PRICE: 0.1
R24 = 330_ohm_5%_0805_0: RES SMD 47K OHM 1% 1/10W 0603; BOARD ID: 2; BOARDID: 4; DIGIKEY-PART NUMBER: 311-47.0KHRCT-ND; MFG Part number: RC0603FR-0747KL; Manufacturer: Yageo; Mfr_Name: Yageo; Mfr_Part#: ERJ-3GEY0R00V; PRICE: 0.1
R25 = 330_ohm_5%_0805_0: RES SMD 1.47M OHM 1% 1/10W 0603; BOARD ID: 2; BOARDID: 4; DIGIKEY-PART NUMBER: 541-1.47MHCT-ND; MFG Part number: CRCW06031M47FKEA; Manufacturer: Vishay Dale; Mfr_Name: Vishay Dale; Mfr_Part#: CRCW06031M47FKEA; PRICE: 0.1; Tolerance: 1%
R26 = 330_ohm_5%_0805_0: RES SMD 147K OHM 1% 1/10W 0603; BOARD ID: 2; BOARDID: 4; DIGIKEY-PART NUMBER: 311-147KHRCT-ND; MFG Part number: RC0603FR-07147KL; Manufacturer: Yageo; Mfr_Name: Yageo; Mfr_Part#: RC0603FR-07147KL; PRICE: 0.1; Tolerance: 1%
R27 R28 = 330_ohm_5%_0805_0: RES SMD 0 OHM JUMPER 1/4W 0603; BOARD ID: 2; BOARDID: 4; DIGIKEY-PART NUMBER: 541-0.0SBCT-ND; MFG Part number: CRCW06030000Z0EAHP; Manufacturer: Vishay Dale; Mfr_Name: Yageo; Mfr_Part#: ERJ-3GEY0R00V; PRICE: 0.17
R29 = 330_ohm_5%_0805_0: RES SMD 9.09K OHM 1% 1/8W 0805; BOARD ID: 2; BOARDID: 4; DIGIKEY-PART NUMBER: 311-9.09KCRTR-ND; MFG Part number: RC0805FR-079K09L; Manufacturer: Yageo; PRICE: 0.1; VOLTAGE: 1%; WATT: 0.125W; Wattage: 0.125W
R30 = 330_ohm_5%_0805_0: RES SMD 47K OHM 1% 1/10W 0603; BOARD ID: 2; BOARDID: 4; DIGIKEY-PART NUMBER: 311-47.0KHRCT-ND; DNP: DNP; MFG Part number: RC0603FR-0747KL; Manufacturer: Yageo; Mfr_Name: Yageo; Mfr_Part#: ERJ-3GEY0R00V; PRICE: 0.1
R31 = 330_ohm_5%_0805_0: RES SMD 2.2 OHM 1% 1/10W 0603; BOARD ID: 2; BOARDID: 4; DIGIKEY-PART NUMBER: 311-2.2HRCT-ND; MFG Part number: RC0603FR-072R2L; Manufacturer: Yageo; Mfr_Name: Yageo; Mfr_Part#: RC0402FR-07100KL; PRICE: 0.1
R32 R34 = 330_ohm_5%_0805_0: RES SMD 1K OHM 1% 1/10W 0603; BOARD ID: 2; BOARDID: 4; DIGIKEY-PART NUMBER: 311-1.00KHRCT-ND; DNP: DNP; MFG Part number: RC0603FR-071KL; Manufacturer: Yageo; Mfr_Name: Yageo; Mfr_Part#: RC0402FR-07100KL; PRICE: 0.1
R33 = 330_ohm_5%_0805_0: RES SMD 100K OHM 1% 1/10W 0603; BOARD ID: 2; BOARDID: 4; DIGIKEY-PART NUMBER: P100KHCT-ND; MFG Part number: ERJ-3EKF1003V; Manufacturer: Panasonic Electronic Components; PRICE: 0.1
R35 = RESISTOR: RES SMD 20 OHM 5% 1/2W 1210; Assy: DNP; BOARD ID: 2; BoardID: 4; DIGIKEY-PART NUMBER: 541-20VCT-ND; MFG Part number: CRCW121020R0JNEA; Manufacturer: Vishay Dale; Price: 0.21; VOLTAGE: 0.5W
R39 = RESISTOR: RES 0.005 OHM 1% 1W 1206; BOARD ID: 2; BoardID: 4; DIGI-KEY PART NO: CSRF1206FT5L00CT-ND; DIGIKEY-PART NUMBER: CSRF1206FT5L00CT-ND; MFG Part number: CSRF1206FT5L00; Manufacturer: Stackpole Electronics Inc.; PART_NUMBER: PRL1632-R005-F-T1; Package: 1206; Price: 0.66; Tolerance: 1%; Wattage: 1W
RT1 = RESISTOR_VAR_2_4: THERM NTC 100KOHM 4250K 0805; BOARD ID: 2; BOARDID: 4; DIGIKEY-PART NUMBER: 490-2451-1-ND; MFG Part number: NCP21WF104J03RA; Manufacturer: Murata Electronics North America; Manufaturer: Cantherm; PRICE: 0.21
SEC1 SEC2 = TEST_POINT: BOARD ID: 2; BoardID: 4
TP-S1 = TEST_POINT: BOARD ID: 2; BOARDID: 4
U2 = PAG1S_11: USB-PD Power Adapter Secondary Side Controller; BOARD ID: 2; BOARDID: 4; MFG Part number: CYPAS111A1-24LQXQ; Manufacturer: CYPRESS SEMICONDUCTOR

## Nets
VBUS-CTRL-G: Q4.4(G) R30.2 R31.2
VBUS_C: C25.1 J1.A4(VBUS_1) J1.B4(VBUS_3) Q4.1(S) Q4.2(S) Q4.3(S) R30.1 U2.18(VBUS_C)
VBUS_IN: C24.1 C26.1 C33.1 C34.1 C35.1 Q4.5(D) Q4.6(D) Q4.7(D) Q4.8(D) R22.2 SEC2.1
VDDD: C15.1 C16.1 R33.2 U2.22(VDDD)
AC-IN-L: F1.1 L1.1
AC-IN-N: CX1.2 LF1.4 N1.1
BD-OUT: BD1.1(DC_OUT_PLUS) C3.1 C39.1 L3.1
FUSE-IN: CX1.1 F1.2 LF1.1
PAG1P-AUXIN: D7.C J2.5 R10.1 R43.2
PAG1P-AUXIN (page PAGE02_PULSE TRANSFORMER BOARD): C1.1 C4.1 J3.5 U1.9(AUXIN)
PAG1P-CS: C11.1 R19.1 U1.7(CS)
PAG1P-OVP-AUX: C9.1 D5.C(K) R7.1 R11.2 U1.10(OVP_AUX)
PAG1P-PULSEIN: R18.1 T2.3 U1.4(PULSEIN)
PAG1P-RT: R2.2 U1.3(RT)
PAG1P-SS: C12.1 R18.2 T2.4 U1.5(SS)
PAG1P-START-RD: D2.C D4.C R9.2 R44.2
PAG1P-START-RR: R8.2 R9.1
PAG1P-VDD700: EF14.1 R8.1
PAG1P-VDD700 (page PAGE02_PULSE TRANSFORMER BOARD): EF13.1 U1.1(VDD700)
PAG1S-CC1: C17.1 D8.C J1.A5(CC1) U2.14(CC1)
PAG1S-CC2: C19.1 D11.C J1.B5(CC2) U2.13(CC2)
PAG1S-CC-COMP: C23.1 C29.1 R26.2 U2.7(CC_COMP/GPIO2)
PAG1S-CC-COMP-RC: C22.1 R26.1
PAG1S-CC-RC: C29.2 R34.1
PAG1S-CSN: C31.1 R37.1 U2.10(CSN)
PAG1S-CSP: C31.2 R38.1 U2.11(CSP)
PAG1S-CV-COMP-RC: C21.1 R25.1
PAG1S-DM-GPIO4: D9.C J1.A7(D-) J1.B7(D-) U2.16(DM_GPIO4)
PAG1S-DP-GPIO5: D10.C J1.A6(D+) J1.B6(D+) U2.17(DP_GPIO5)
PAG1S-EA-OUT: C20.2 C21.2 C22.2 C23.2 U2.8(EA_OUT)
PAG1S-FB: C20.1 C28.2 R25.2 U2.9(FB)
PAG1S-FB-RC: C28.1 R32.1
PAG1S-GPIO0: R33.1 RT1.2 U2.5(GPIO0)
PAG1S-GPIO1: R27.2 U2.6(GPIO1)
PAG1S-GPIO3: R34.2 U2.12(GPIO3)
PAG1S-SR-GDRV: R23.1 U2.1(SR_GDRV)
PAG1S-SR-SENSE: R29.1 U2.3(SR_SEN)
PAG1S-SR-VSS: R28.1 U2.2(SR_VSS)
PAG1S-VBUS-IN: C27.1 R22.1 R32.2 U2.20(VBUS_IN)
PAG1S-VCCD: C14.1 U2.21(VCCD)
PAG1S-XRES: U2.4(XRES)
PE_GND: BD1.4(DC_OUT_MINUS) C2.2 C3.2 C5.2 C6.2 C8.2 C36.2 C39.2 D1.A EF16.1 J2.3 R3.2 R4.2 T1.3(AUX1)
PE_GND1: C1.2 C4.2 C9.2 C11.2 C12.2 D5.A J3.3 R2.1 R11.1 U1.6(GND)
PE_GND_2: EF15.1 TP-P1.1
PRI-FET-D: D6.A Q1.D T1.6(IN2)
PRI-FET-GATE: J2.1 R17.1 R40.1 R45.1
PRI-FET-GATE (page PAGE02_PULSE TRANSFORMER BOARD): J3.1 U1.8(GD)
PRI-FET-S: C37.2 J2.2 Q1.S Q1.SK R1.1 R3.1 R4.1
PRI-FET-S (page PAGE02_PULSE TRANSFORMER BOARD): J3.2 R19.2
PULSE-TXR-SEC1: J4.2 R20.1
PULSE-TXR-SEC1 (page PAGE03_SECONDARY BOARD): J5.1 R27.1
PULSE-TXR-SEC2: J4.1 R21.1
SE_GND: C14.2 C15.2 C16.2 C17.2 C19.2 C24.2 C26.2 C27.2 C33.2 C34.2 C35.2 J5.2 Q3.1(S) Q3.2(S) Q3.3(S) R24.1 R28.2 R35.1 R37.2 R39.2 RT1.1 TP-S1.1 U2.15(VSS) U2.25(EPAD)
SR-FET-D: C30.1 Q3.5(D) Q3.6(D) Q3.7(D) Q3.8(D) R29.2 SEC1.1
SR-FET-G: Q3.4(G) R23.2 R24.2
SR-FET-SNUB: C30.2 R35.2
TX-AUX-RD1: D3.A R5.1
TX-AUX-RD2: D13.A R41.1
TXR-AUX1: C36.1 J2.4 R5.2 T1.5(AUX3)
TXR-AUX1 (page PAGE02_PULSE TRANSFORMER BOARD): J3.4 R7.2
TXR-AUX-NPN-B1: D1.K Q2.1(B) R6.2
TXR-AUX-NPN-C1: C8.1 D3.C Q2.3(C) R6.1
TXR-AUX-NPN-E: D7.A Q2.2(E) R10.2
TYPE-C_GND: C25.2 C32.1 D8.A D9.A D10.A D11.A J1.A1(GND_1) J1.B1(GND_3) R36.2 R38.2 R39.1
VCLAMP-RCD: C10.2 R13.2 R14.2 R16.2
VDC_IN: C2.1 C5.1 C6.1 C10.1 L3.2 R12.1 R15.1 R44.1 T1.2(IN1)
N14642334: BD1.3(AC_IN_1) CX2.1 D4.A EF9.1
N14642346: BD1.2(AC_IN) CX2.2 D2.A EF10.1
N15949532: C18.2 U2.24(SR_CPP)
N15949534: C18.1 U2.23(SR_CPN)
N15949698: C32.2 J1.MH1 J1.MH2 J1.MH3 J1.MH4 J1.S1 J1.S2 R36.1
N15949882: R31.1 U2.19(VBUS_CTRL)
N15963322: R21.2 T2.2
N15963346: C13.2 R20.2
N15963350: C13.1 T2.1
N15983010: R12.2 R13.1 R15.2 R16.1
N15985596: C38.1 D12.A R17.2
N16013994: C37.1 C38.2 Q1.G R1.2 R45.2
N16032372: D6.C R14.1
N16078751: D13.C R43.1
N16079880: R41.2 T1.1(AUX2)
N16095646: EF11.1 LF1.2
N16095654: EF12.1 LF1.3
N16166937: D12.C R40.2

Not connected (* = marked no-connect by the designer): J1 A8(SBU1)* B8(SBU2)*

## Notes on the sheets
sheet 1
- 0805
- 0805
- 6T
- 2T
- 45W PULSE TRANSFORMER BOARD
sheet 2
- 45W-SECONDARY SIDE BOARD
- SECONDARY SIDE
- USB TYPE C RECEPTACLE
- FL3(BLACK)
- D
- S
- 0805
- 1210
- G
- 0805
- Connectors from Pulse Transformer PCB
- FL4(CLEAR)
- PLACE CLOSE TO PAG1S
- 45W SECONDARY SIDE
sheet 3
- RELEASE
  DATE
- REV NO
- CHANGES
- 1
- DEVELOPED OVER CY-SD1124
- 25-08-2020
- C34,C35 CAPS CHANGED FROM 330uF TO 470uF
  Aluminum - Polymer Capacitors.
- 2
- 01-01-2021
- 3
- C36 changed to DNP
  R17 changed to 560 ohm; 0603
  R40 changed to 10 ohm; 0603
  D12- BAT54J,115; diode added in turn off path
  R3,R4 changed to 0.39 ohm; RCWE1206R390FKEA
  C30 changed to 820pF, 0805, CGJ4C3C0G2D821J060AA
  R35, changed to  20 ohm, CRCW121020R0JNEA
  R25 changed to 1.47Meg ohm; 0603
  R26 changed to 147kohm; 0603
  J6 changed to DX07S016JA3R1500; USB type-c receptacle
- 10-03-2022
- REVISION HISTORY
sheet 4
- 45W CHARGER - PRIMARY SIDE BOARD
- ALL 1206
  PACKAGE
- 600V, 4A
- 20T
- 6T
- 1206
- 1206
- 1206
- 20T
- 1KV, 1.5A
- 30T
- 16V
- 0805
- 0805
- 2A, 250V
- 1206
- 1206
- 45W PRIMARY SIDE
